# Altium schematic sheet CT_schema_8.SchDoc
size 391 x 238 mm
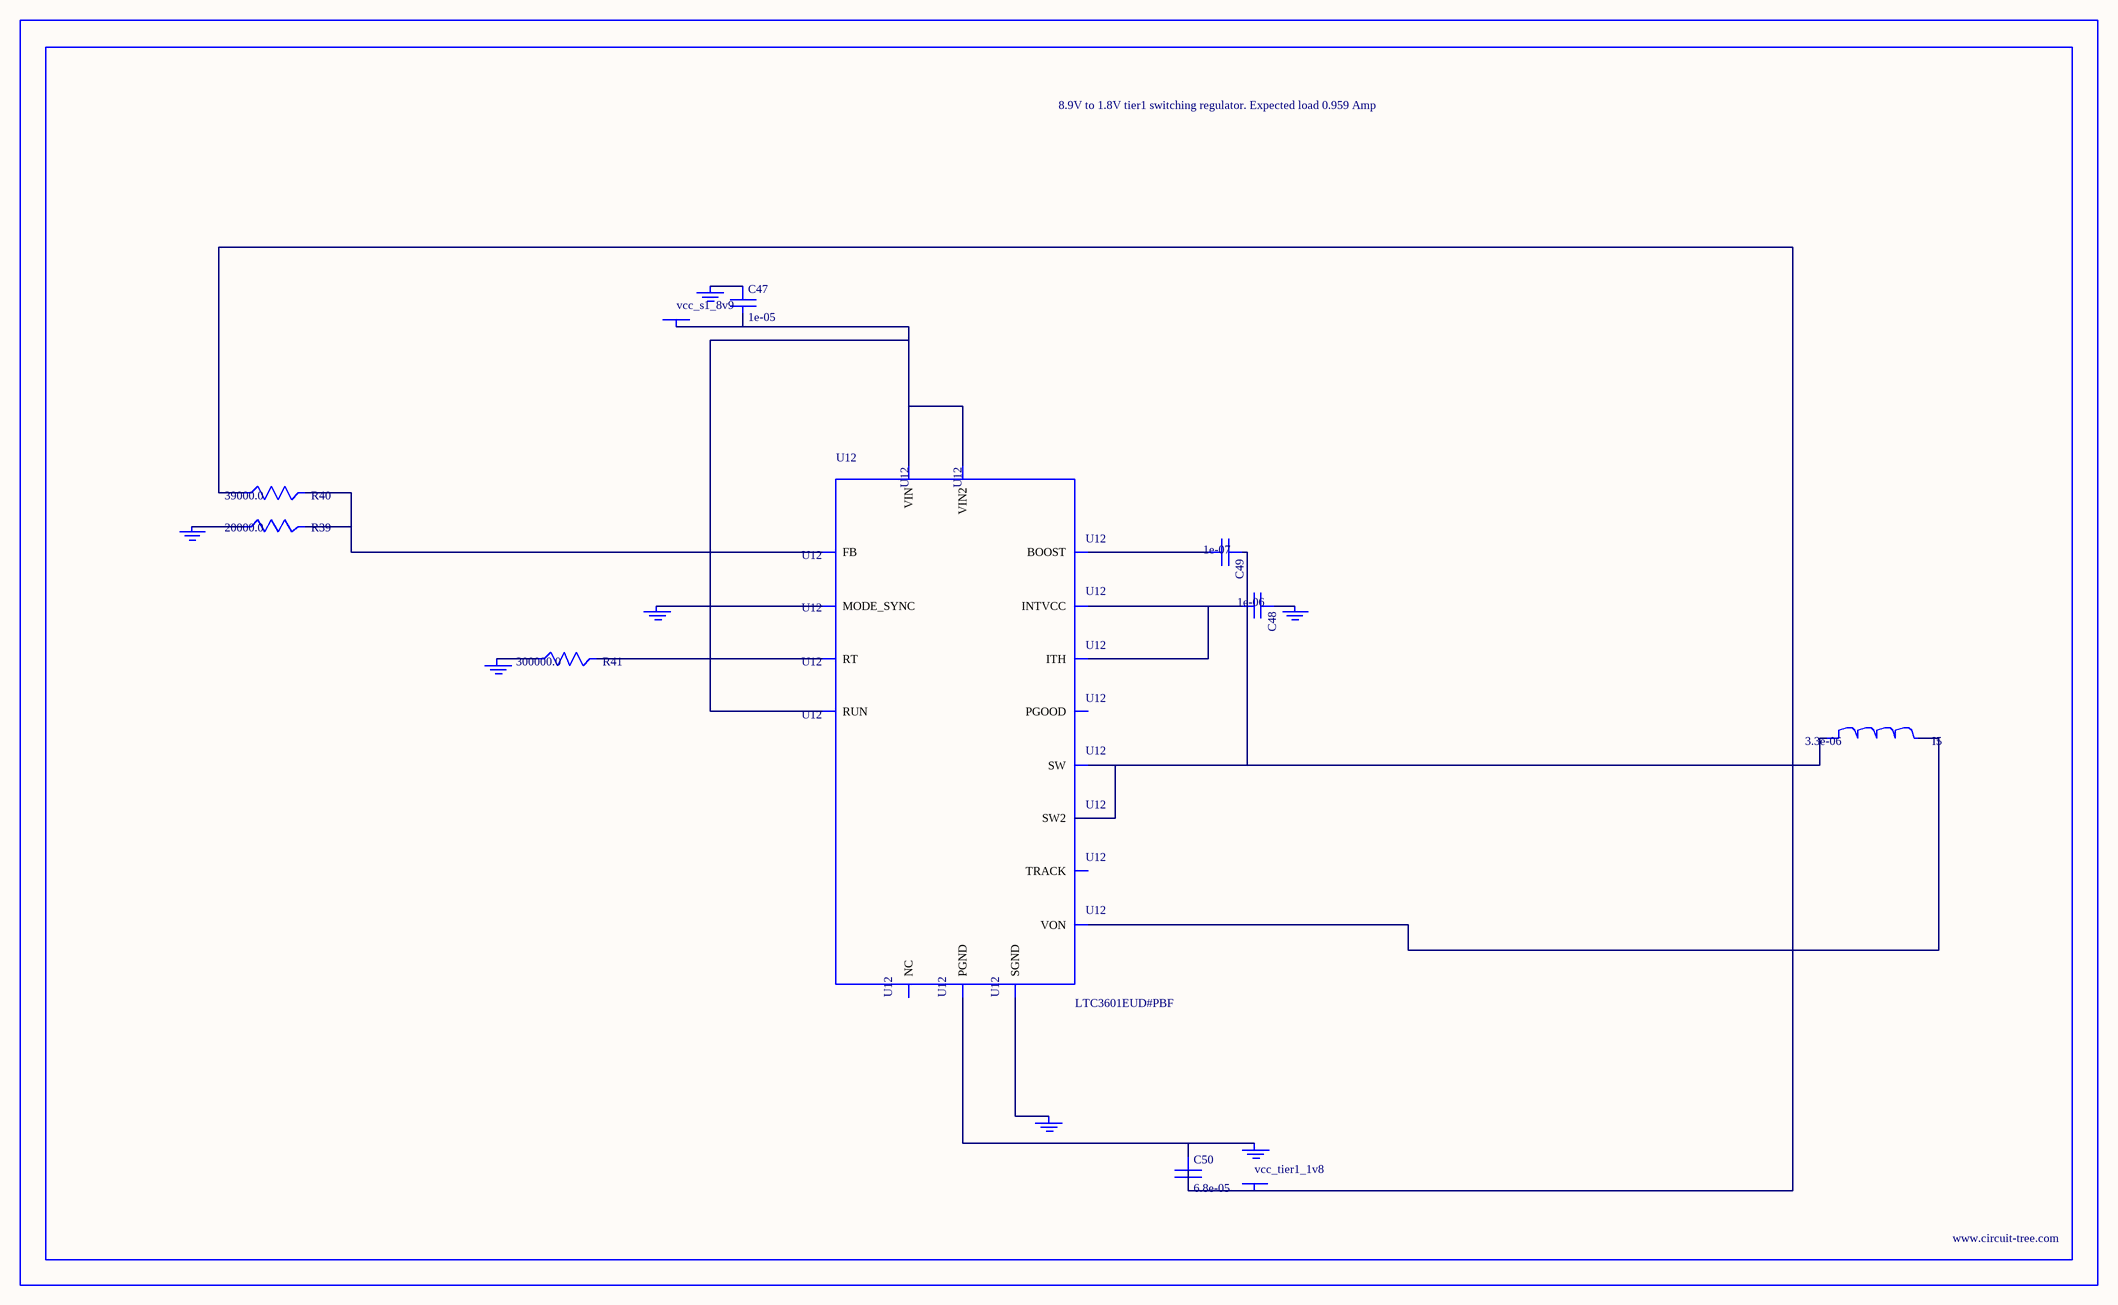
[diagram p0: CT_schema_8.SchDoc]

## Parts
BORDER7  (no value)
C47  1e-05  [C0805]
C48  1e-06  [C0603]
C49  1e-07  [C0402]
C50  6.8e-05  [2220]
GND_INSTANCE_7_0  (no value)
GND_INSTANCE_7_1  (no value)
GND_INSTANCE_7_2  (no value)
GND_INSTANCE_7_3  (no value)
GND_INSTANCE_7_4  (no value)
GND_INSTANCE_7_5  (no value)
GND_INSTANCE_7_6  (no value)
I5  3.3e-06  [WE-HCI_7030/7040/7050]
POWER_INSTANCE_7_0  vcc_s1_8v9
POWER_INSTANCE_7_1  vcc_tier1_1v8
R39  20000.0  [R0603]
R40  39000.0  [R0603]
R41  300000.0  [R0603]
U12  LTC3601EUD#PBF  [QFN-16_EP]

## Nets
NetC47_1: C47.1 GND_INSTANCE_7_5.0(GND)
NetC47_2: C47.2 POWER_INSTANCE_7_0.0(PWR) U12.14(RUN) U12.15(VIN) U12.16(VIN2)
NetC48_1: C48.1 GND_INSTANCE_7_1.0(GND)
NetC48_2: C48.2 U12.7(INTVCC) U12.12(ITH)
NetC49_1: C49.1 I5.1 U12.3(SW) U12.4(SW2)
NetC49_2: C49.2 U12.6(BOOST)
NetC50_1: C50.1 GND_INSTANCE_7_6.0(GND) U12.17(PGND)
NetC50_2: C50.2 I5.2 POWER_INSTANCE_7_1.0(PWR) R40.1 U12.8(VON)
NetGND_INSTANCE_7_0_0: GND_INSTANCE_7_0.0(GND) U12.1(MODE_SYNC)
NetGND_INSTANCE_7_2_0: GND_INSTANCE_7_2.0(GND) U12.9(SGND)
NetGND_INSTANCE_7_3_0: GND_INSTANCE_7_3.0(GND) R41.1
NetGND_INSTANCE_7_4_0: GND_INSTANCE_7_4.0(GND) R39.1
NetR39_2: R39.2 R40.2 U12.11(FB)
NetR41_2: R41.2 U12.10(RT)

Not connected (* = marked no-connect by the designer): U12 2(PGOOD) 5(NC) 13(TRACK)

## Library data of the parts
BORDER7 = BORDER_PAGE7
C47 = C0805C106K8RACTU
C48 = C0603C105K3RACTU
C49 = C0402C104K3RACTU
C50 = C5750X5R1A686M
GND_INSTANCE_7_0-GND_INSTANCE_7_6 = GND
I5 = 744314330
POWER_INSTANCE_7_0 POWER_INSTANCE_7_1 = PWR
R39 = RC0603JR-0720KL
R40 = RC0603JR-0739KL
R41 = RC0603JR-07300KL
